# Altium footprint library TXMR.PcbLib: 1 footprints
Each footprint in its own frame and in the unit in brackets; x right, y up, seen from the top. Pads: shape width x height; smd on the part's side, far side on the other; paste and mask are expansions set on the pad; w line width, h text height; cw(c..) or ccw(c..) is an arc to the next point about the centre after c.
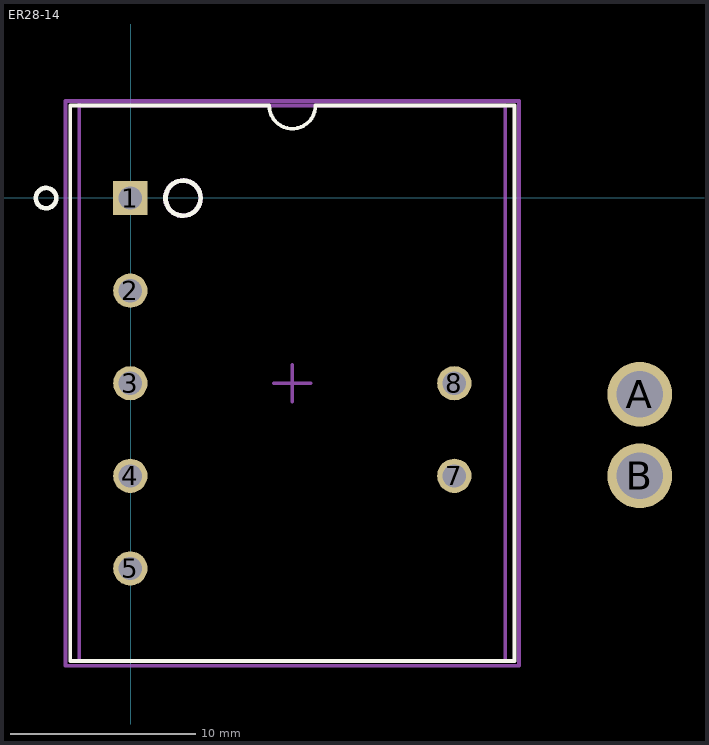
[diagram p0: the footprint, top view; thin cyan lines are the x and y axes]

## ER28-14 [mm]
pads (9):
  rect 1.85x1.85 hole 1.25: 1(-0.018,-0.006)
  round 1.85 hole 1.25: 2(-0.018,-5.006) 3(-0.018,-10.006) 4(-0.018,-15.006) 5(-0.018,-20.006) 7(17.482,-15.006) 8(17.482,-10.006)
  round 3.5 hole 2.5: A(27.5,-10.6) B(27.5,-15.006)
Top Overlay:
  circle w0.254: c2.832,-0.006 r0.95
  circle w0.254: c-4.568,-0.006 r0.552
  lines w0.2: -3.268,4.994 -3.268,-25.006 20.732,-25.006 20.732,4.994 9.982,4.994 cw(c8.732,4.994) 7.482,4.994 -3.258,4.994
M5 Assembly Top:
  text ".Designator" at -1.8,-0.514 h1.02
M13 Component Bodies Top:
  circle w0.254: c2.832,-0.006 r0.95
  lines w0.2: -2.768,4.994 20.232,4.994 20.232,-25.006 -2.768,-25.006 -2.768,5.244
M15 Courtyards Top:
  lines w0.2: 7.732,-10.006 9.732,-10.006 ; 8.732,-11.006 8.732,-9.006 ; -3.518,-25.256 20.982,-25.256 20.982,5.244 -3.518,5.244 -3.518,-25.256
  text ".Designator" at 8.732,-10.006 h0.5
3D body "070-5565.stp": height 36.2, standoff -4.3, extent -2.598,-24.806 20.062,4.714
